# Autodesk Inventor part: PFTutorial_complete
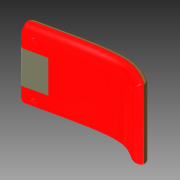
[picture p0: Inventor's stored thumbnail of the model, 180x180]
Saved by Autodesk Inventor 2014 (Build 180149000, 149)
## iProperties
Created: 2008-04
Part Number: PFTutorial_complete
Document SubType Name: Modeling
Designer: gpbassi
Density: 1.06 g/cm^3
Material: ABS Plastic
Mass: 75.0509 g
Surface Area: 950.009 cm^2
Volume: 70.8027 cm^3
Appearance: Smooth - White
Author: ATP
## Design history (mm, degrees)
sketch "SpineSketch"
  geometry: 4 further points
  constraints: 4 other
node "GrillWorkPlane"
node "RestWorkPlane"
node "BossWorkPlane1"
sketch "BossSketch1"
  geometry: 2 further points
node "BossWorkPlane2"
sketch "BossSketch2"
  geometry: 2 further points
sketch "Revolve_NewBody"
  geometry: L1 (-11.76, 31.812)-(-11.76, 29.5); L2 (-11.76, 29.5)-(-7.25, 29.5); L3 (-7.25, 29.5)-(-7.25, 28.5); L4 (-7.25, 28.5)-(-11.76, 28.5); L5 (-11.76, 28.5)-(-11.76, 25.75); L6 (-11.76, 25.75)-(-8, 25.75); L7 (-8, 25.75)-(-8, 17.5); L8 (-8, 17.5)-(0, 17.5); L9 (0, 17.5)-(0, 0); L10 (0, 37.5)-(0, 17.5); A1 r 15 centre (0, 22.5) between (0, 37.5) and (-11.76, 31.812); 2 further points
  constraints: 20 end point, 5 parallel, 3 collinear, 2 coincident, 2 perpendicular, 2 point on circle, 1 centre point, 1 horizontal, 1 point on line
  dimensions: "d121" = 15 radius of A1; "d122" = 20 distance of L10.start L8.end; "d123" = 8 distance of L7.end L8.end; "d124" = 17.5 distance from line of L8 point (0, 0); "d125" = 7.25 distance between parallel lines of L3 L10; "d126" = 11.75984 distance between parallel lines of L1 L10; "d127" = 8.25 distance between parallel lines of L6 L8; "d128" = 12 distance between parallel lines of L2 L8; "d129" = 11 distance between parallel lines of L4 L8
node "SectionWorkPlane"
sketch "SectionSketch"
  geometry: L1 (17, 0)-(-19, 0) reference; L2 (0, -51)-(0, 53) reference; L3 (-14, -39.559)-(-14, 39.559); L4 (5, 52.635)-(5, -52.635); A1 r 14 centre (0, -39.559) between (-14, -39.559) and (5, -52.635); A2 r 14 centre (0, 39.559) between (5, 52.635) and (-14, 39.559); 2 further points
  constraints: 8 end point, 5 point on circle, 3 point on line, 3 symmetric about line, 2 centre point, 1 horizontal, 1 parallel, 1 perpendicular, 1 tangent, 1 vertical, 1 other
  dimensions: "d96" = 19 distance between parallel lines of L3 L4; "d97" = 5 distance between parallel lines of L4 L2
sweep "Sweep1" sketch "SectionSketch" dims "d62" = 0
extrude_surface "PartingSurface" dims "d63" = 134, "d64" = 0
sketch "GrillSketch"
  geometry: L1 (-59.25, -36.361)-(-59.25, 36.361); L2 (-100.75, 36.361)-(-100.75, -36.361); L3 (-62, -50)-(-62, 50); L4 (-66, -50)-(-66, 50); L5 (-70, -50)-(-70, 50); L6 (-74, -50)-(-74, 50); L7 (-78, -50)-(-78, 50); L8 (-82, -50)-(-82, 50); L9 (-86, -50)-(-86, 50); L10 (-90, -50)-(-90, 50); L11 (-94, -50)-(-94, 50); L12 (-98, -50)-(-98, 50); L13 (-102, 0)-(-57, 0) reference; L14 (-80, -47)-(-80, 47) reference; A1 r 32 centre (-80, -12) between (-100.75, -36.361) and (-59.25, -36.361); A2 r 32 centre (-80, 12) between (-59.25, 36.361) and (-100.75, 36.361); A3 r 32 centre (-80, 12) between (-106.819, -5.457) and (-52.691, -4.68); A4 r 32 centre (-80, -12) between (-52.691, 4.68) and (-106.819, 5.457)
  constraints: 28 end point, 8 point on circle, 4 centre point, 3 parallel, 3 symmetric about line, 1 coincident, 1 horizontal, 1 perpendicular, 1 vertical, 4 other
  dimensions: "d82" = 32 radius of A1; "d83" = 20.75 distance between parallel lines of L2 L14; "d84" = 32 radius of A2; "d85" = 32 radius of A3
sketch "RestSketch"
  geometry: L1 (34, 0)-(-25, 0); L2 (34, 0)-(-25, 0); L3 (-7.849, 32.548)-(-13.735, 2.71); L4 (-8, -31)-(-8, -11.489); L5 (7.849, -32.548)-(13.735, -2.71); L6 (8, 31)-(8, 11.489); A1 r 8 centre (0, -31) between (-8, -31) and (7.849, -32.548); A2 r 8 centre (0, 31) between (8, 31) and (-7.849, 32.548); A3 r 14 centre (0, 0) between (13.735, -2.71) and (8, 11.489); A4 r 14 centre (0, 0) between (-13.735, 2.71) and (-8, -11.489)
  constraints: 12 end point, 8 point on circle, 6 tangent, 4 centre point, 2 horizontal, 1 parallel, 1 perpendicular, 1 point on line
feature "BatterySplitSurface" dims "d120" = 0.254 (derived)
workpoint "Work Point3"
workpoint "Work Point4"
shell "Shell1" dims "d133" = 1.5
split "Split2"
  body "Solid1"
feature "Grill1" dims "d136" = 2, "d137" = 0, "d138" = 0, "d139" = 1.3, "d140" = 0.2, "d141" = 2.5, "d142" = 0.5, "d143" = 0, "d144" = 5, "d145" = 0, "d146" = 0, "d147" = 0, "d148" = 119.99372
feature "Rule Fillet1" dims "d149" = 0.5, "d150" = 1 deg
feature "Rest1" dims "d151" = 5, "d152" = 0, "d153" = 0, "d154" = 0, "d155" = 0, "d156" = 0, "d157" = 1.5
feature "Lip1" dims "d158" = 1, "d159" = 0.75, "d160" = 0, "d161" = 0, "d162" = 0, "d163" = 0.5
feature "Lip2" dims "d164" = 1, "d165" = 0.75, "d166" = 0, "d167" = 0, "d168" = 0, "d169" = 0
split "Split3"
  body "Solid3"
workplane "Work Plane11"
workplane "Work Plane12"
feature "Lip3" dims "d172" = 0.8, "d173" = 0.75, "d174" = 0, "d175" = 0, "d176" = 0, "d177" = 0
feature "Lip4" dims "d178" = 0.8, "d179" = 0.75, "d180" = 0, "d181" = 0, "d182" = 0, "d183" = 0
sketch "Sketch13"
  geometry: L1 (0, 0)-(0, 48) reference; L2 (-1.5, 48)-(0, 48) reference; L3 (-1.5, 0)-(0, 0) reference; 3 further points
  constraints: 2 point on line
  dimensions: "d184" = 7.5 distance from line of point (0, 7.5) L3; "d185" = 7.5 distance from line of point (0, 40.5) L2 (derived)
feature "Snap Fit1" sketch "Sketch13" dims "d186" = 4, "d187" = 0.5, "d188" = 0.3, "d189" = 5, "d190" = 2, "d191" = 0.5, "d192" = 0.5, "d193" = 0.5
feature "Rule Fillet2" dims "d194" = 0.2
feature "Boss1" dims "d195" = 0.3, "d196" = 8, "d197" = 1.5, "d198" = 0.5, "d199" = 7, "d200" = 1.5, "d201" = 3, "d202" = 2.5 deg, "d203" = 2.5 deg, "d204" = 2.5 deg, "d205" = 2.5 deg, "d206" = 90 deg, "d209" = 2, "d210" = 2, "d211" = 10, "d212" = 0, "d213" = 10 deg, "d214" = 2.5 deg, "d215" = 0, "d216" = 0, "d217" = 0, "d267" = 0, "d268" = 360 deg
feature "Boss2" dims "d218" = 0.3, "d219" = 8, "d220" = 3, "d221" = 9.5, "d222" = 2 deg, "d223" = 1 deg, "d226" = 1.5, "d227" = 2, "d228" = 6, "d229" = 1, "d230" = 10 deg, "d231" = 1.5 deg, "d232" = 0.2, "d233" = 0.2, "d234" = 0, "d269" = 0, "d270" = 360 deg
hole "Hole1" diameter "d237" = 10; stored, may be unused: countersink angle "d241" = 90 deg, drill point angle "d243" = 118 deg; dims "d235" = 10, "d236" = 10, "d238" = 6, "d239" = 4, "d240" = 2, "d242" = 2
hole "Hole2" diameter "d246" = 10; stored, may be unused: countersink angle "d250" = 90 deg, drill point angle "d252" = 118 deg; dims "d244" = 10, "d245" = 10, "d247" = 6, "d248" = 4, "d249" = 2, "d251" = 2
hole "Hole3" diameter "d255" = 20; stored, may be unused: countersink angle "d259" = 90 deg, drill point angle "d261" = 118 deg; dims "d253" = 10, "d254" = 10, "d256" = 6, "d257" = 4, "d258" = 2, "d260" = 2
derived "Control_Button_Solid.ipt"
feature "Move Body1"
combine "Combine1"
  body "Solid6"
revolve "Revolution1" stored, may be unused: angle "d266" = 90 deg
fillet "Fillet1" dims "d98" = 8
fillet "Fillet2" dims "d99" = 3
workpoint "Work Point1"
workpoint "Work Point2"
body "Srf1"
sketch "BatterySketch"
  geometry: L1 (-10.134, -25)-(-18, -25); L2 (-18, -25)-(-18, 25); L3 (-18, 25)-(-10.134, 25); L4 (-9.134, 24)-(-9.134, -24); L5 (2, 0)-(-25, 0) reference; A1 r 1 centre (-10.134, -24) between (-10.134, -25) and (-9.134, -24); A2 r 1 centre (-10.134, 24) between (-9.134, 24) and (-10.134, 25)
  constraints: 10 end point, 4 point on circle, 4 tangent, 2 centre point, 2 horizontal, 2 parallel, 2 perpendicular, 1 equal radius, 1 other
  dimensions: "d104" = 1 radius of A1
body "Srf3"
body "Srf4"
body "Srf2"
feature "Solid1::Control_Button_Solid.ipt" dims "d262" = 10
tag "TaggingFeature1"
body "Solid7"
extrude_surface "ExtrusionSrf3" dims "d105" = 36, "d106" = 0
patch "Boundary Patch1" dims "d107" = 0, "d108" = 0, "d109" = 0
body "Solid2"
body "Solid4"
body "Solid5"
other parameters: "d102" = 24, "d110" = 4.5, "d115" = 11.75, "d134" = 2.5, "d135" = 5, "d170" = -15, "d171" = -15, "d263" = 35, "d264" = 24, "d265" = 0
